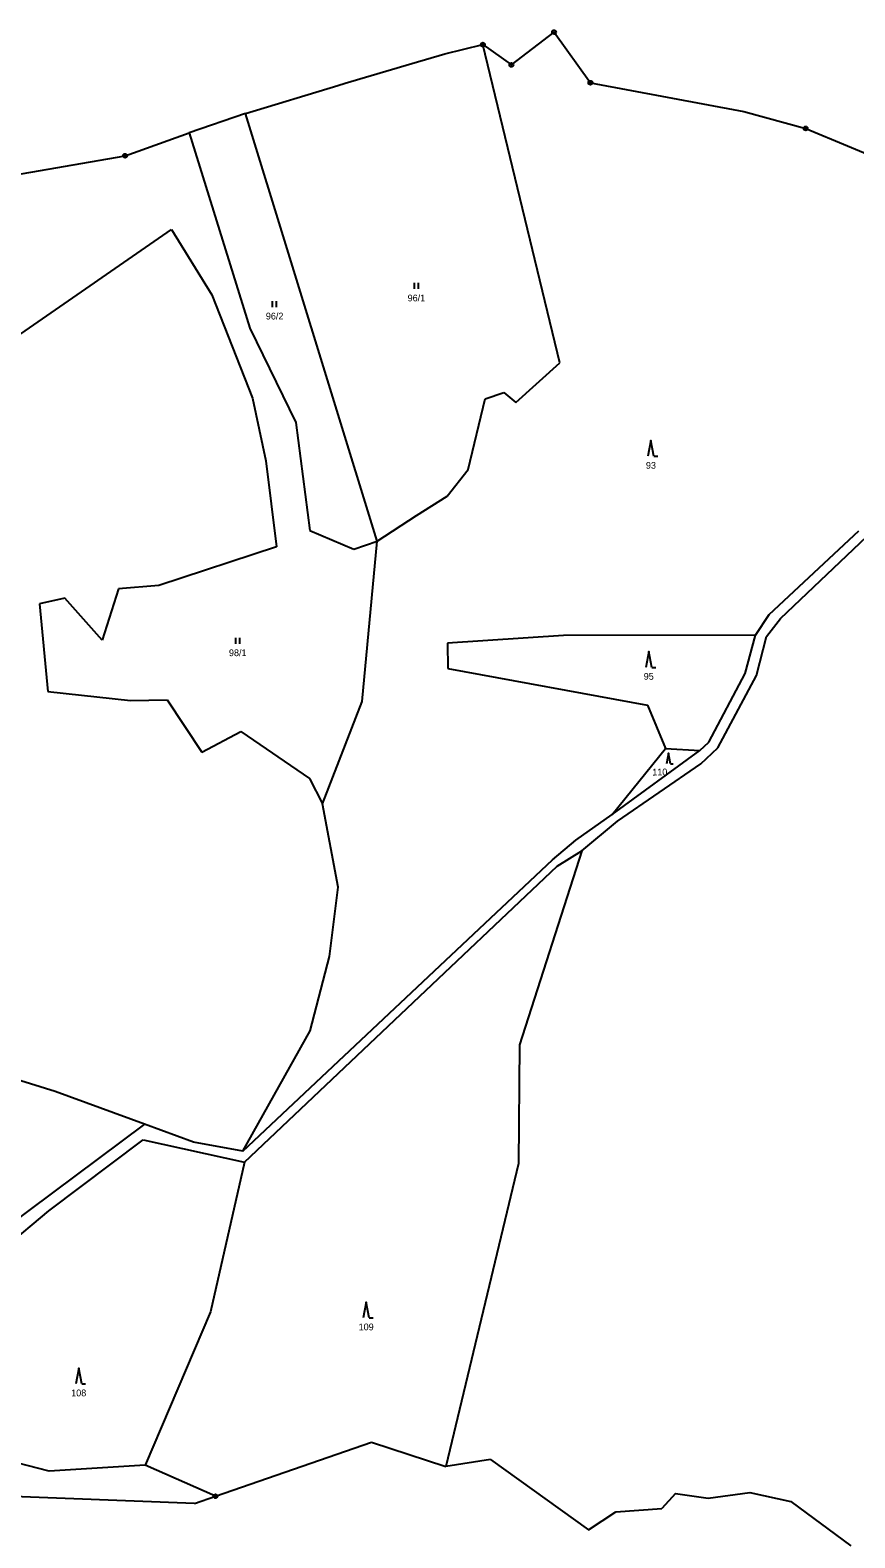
# Model space of a CAD drawing. Extents: x -601877 to -599786, y -1122905 to -1121218.
# Drawn here: x -601684.6 to -601476.9, y -1122139.9 to -1121760.1 of the extents above; entities that cross this region are included whole.
import ezdxf
from ezdxf.enums import TextEntityAlignment as Align

# ---------------------------------------------------------------- set-up
doc = ezdxf.new("R2010")
doc.units = 0
doc.header["$LTSCALE"] = 0.68
for name, color, linetype, lineweight in [('1', 7, 'Continuous', 25), ('3', 7, 'Continuous', 25), ('8', 7, 'Continuous', 25)]:
    doc.layers.add(name, color=color, linetype=linetype, lineweight=lineweight)
doc.layers.add('2', color=7, linetype='Continuous')

msp = doc.modelspace()

# ---------------------------------------------------------------- linework, layer by layer
at = {"layer": '1'}
for p, q in [((-601563.4, -1121768.8), (-601552.65, -1121760.56)), ((-601552.65, -1121760.56), (-601543.5, -1121773.3)), ((-601588.47, -1121768.49), (-601580.13, -1121766.04)), ((-601580.13, -1121766.04), (-601570.58, -1121763.7)), ((-601570.58, -1121763.7), (-601563.4, -1121768.8)), ((-601551.18, -1121843.87), (-601570.58, -1121763.7)), ((-601605.25, -1121773.43), (-601588.47, -1121768.49)), ((-601630.36, -1121781.07), (-601607.07, -1121773.97)), ((-601607.07, -1121773.97), (-601605.25, -1121773.43)), ((-601543.5, -1121773.3), (-601504.87, -1121780.53)), ((-601630.36, -1121781.07), (-601644.55, -1121785.9)), ((-601597.19, -1121888.8), (-601630.36, -1121781.07)), ((-601504.87, -1121780.53), (-601489.29, -1121784.81)), ((-601489.29, -1121784.81), (-601462.41, -1121796.01)), ((-601660.68, -1121791.7), (-601644.55, -1121785.9)), ((-601644.55, -1121785.9), (-601629.23, -1121835.11)), ((-601707.88, -1121799.89), (-601660.68, -1121791.7)), ((-601686.97, -1121836.54), (-601649.03, -1121810.29)), ((-601649.03, -1121810.29), (-601638.8, -1121826.74)), ((-601638.8, -1121826.74), (-601628.63, -1121852.77)), ((-601629.23, -1121835.11), (-601617.68, -1121858.88)), ((-601562.25, -1121853.83), (-601551.18, -1121843.87)), ((-601628.63, -1121852.77), (-601625.22, -1121868.57)), ((-601574.32, -1121870.72), (-601569.99, -1121852.93)), ((-601569.99, -1121852.93), (-601565.33, -1121851.33)), ((-601565.33, -1121851.33), (-601562.25, -1121853.83)), ((-601617.68, -1121858.88), (-601614.16, -1121886.07)), ((-601625.22, -1121868.57), (-601622.52, -1121890.19)), ((-601579.53, -1121877.42), (-601574.32, -1121870.72)), ((-601587.31, -1121882.3), (-601579.53, -1121877.42)), ((-601597.19, -1121888.8), (-601587.31, -1121882.3)), ((-601614.16, -1121886.07), (-601603.05, -1121890.8)), ((-601498.48, -1121907.26), (-601475.94, -1121886.16)), ((-601495.65, -1121908.27), (-601472.22, -1121886.04)), ((-601622.52, -1121890.19), (-601652.22, -1121899.94)), ((-601603.05, -1121890.8), (-601597.19, -1121888.8)), ((-601600.94, -1121929.2), (-601597.19, -1121888.8)), ((-601675.87, -1121903.13), (-601682.19, -1121904.61)), ((-601666.46, -1121913.75), (-601675.87, -1121903.13)), ((-601662.34, -1121900.82), (-601666.46, -1121913.75)), ((-601652.22, -1121899.94), (-601662.34, -1121900.82)), ((-601682.19, -1121904.61), (-601680.1, -1121926.63)), ((-601501.96, -1121912.48), (-601498.48, -1121907.26)), ((-601499.17, -1121912.79), (-601495.65, -1121908.27)), ((-601550.26, -1121912.59), (-601579.52, -1121914.46)), ((-601579.52, -1121914.46), (-601579.41, -1121920.85)), ((-601501.96, -1121912.48), (-601550.26, -1121912.59)), ((-601504.52, -1121922.08), (-601501.96, -1121912.48)), ((-601501.64, -1121922.66), (-601499.17, -1121912.79)), ((-601579.41, -1121920.85), (-601529.14, -1121930.09)), ((-601513.64, -1121939.41), (-601504.52, -1121922.08)), ((-601511.43, -1121940.82), (-601501.64, -1121922.66)), ((-601680.1, -1121926.63), (-601659.31, -1121928.94)), ((-601659.31, -1121928.94), (-601650.07, -1121928.77)), ((-601650.07, -1121928.77), (-601641.38, -1121941.98)), ((-601610.95, -1121954.95), (-601600.94, -1121929.2)), ((-601529.14, -1121930.09), (-601524.6, -1121941.04)), ((-601641.38, -1121941.98), (-601631.49, -1121936.7)), ((-601631.49, -1121936.7), (-601614.22, -1121948.53)), ((-601538.03, -1121957.63), (-601524.6, -1121941.04)), ((-601524.6, -1121941.04), (-601515.92, -1121941.54)), ((-601515.92, -1121941.54), (-601513.64, -1121939.41)), ((-601515.67, -1121944.9), (-601511.43, -1121940.82)), ((-601538.03, -1121957.63), (-601515.92, -1121941.54)), ((-601536.67, -1121959.31), (-601515.67, -1121944.9)), ((-601614.22, -1121948.53), (-601610.95, -1121954.95)), ((-601606.99, -1121975.98), (-601610.95, -1121954.95)), ((-601547.16, -1121964.1), (-601538.03, -1121957.63)), ((-601545.69, -1121966.81), (-601536.67, -1121959.31)), ((-601545.69, -1121966.81), (-601561.35, -1122015.65)), ((-601553.08, -1121969.1), (-601547.16, -1121964.1)), ((-601551.87, -1121970.64), (-601545.69, -1121966.81)), ((-601631.03, -1122042.46), (-601553.08, -1121969.1)), ((-601630.64, -1122045.2), (-601551.87, -1121970.64)), ((-601609.2, -1121993.4), (-601606.99, -1121975.98)), ((-601614.09, -1122012.13), (-601609.2, -1121993.4)), ((-601631.03, -1122042.46), (-601614.09, -1122012.13)), ((-601678.29, -1122027.39), (-601711.28, -1122017.26)), ((-601561.35, -1122015.65), (-601561.61, -1122045.55)), ((-601655.82, -1122035.62), (-601678.29, -1122027.39)), ((-601655.82, -1122035.62), (-601690.54, -1122061.59)), ((-601643.42, -1122040.16), (-601655.82, -1122035.62)), ((-601679.9, -1122057.48), (-601656.12, -1122039.63)), ((-601656.12, -1122039.63), (-601630.64, -1122045.2)), ((-601631.03, -1122042.46), (-601643.42, -1122040.16)), ((-601630.64, -1122045.2), (-601639.18, -1122082.95)), ((-601561.61, -1122045.55), (-601579.93, -1122121.85)), ((-601690.9, -1122066.7), (-601679.9, -1122057.48)), ((-601639.18, -1122082.95), (-601655.62, -1122121.57)), ((-601679.83, -1122123.03), (-601711.13, -1122115.08)), ((-601637.92, -1122129.37), (-601598.61, -1122115.78)), ((-601598.61, -1122115.78), (-601579.93, -1122121.85)), ((-601655.62, -1122121.57), (-601679.83, -1122123.03)), ((-601637.92, -1122129.37), (-601655.62, -1122121.57)), ((-601568.68, -1122120.13), (-601579.93, -1122121.85)), ((-601568.68, -1122120.13), (-601543.94, -1122137.81)), ((-601643.19, -1122131.19), (-601717.39, -1122128.37)), ((-601643.19, -1122131.19), (-601637.92, -1122129.37)), ((-601522.04, -1122128.68), (-601525.53, -1122132.5)), ((-601522.04, -1122128.68), (-601513.86, -1122129.86)), ((-601513.86, -1122129.86), (-601503.35, -1122128.43)), ((-601503.35, -1122128.43), (-601493.03, -1122130.72)), ((-601493.03, -1122130.72), (-601477.88, -1122141.9)), ((-601543.94, -1122137.81), (-601537.1, -1122133.29)), ((-601537.1, -1122133.29), (-601525.53, -1122132.5))]:
    msp.add_line(p, q, dxfattribs=at)
at = {"layer": '3'}
for p, q in [((-601587.831, -1121825.25), (-601587.831, -1121823.75)), ((-601586.83, -1121825.25), (-601586.83, -1121823.75)), ((-601623.531, -1121829.82), (-601623.531, -1121828.32)), ((-601622.53, -1121829.82), (-601622.53, -1121828.32)), ((-601527.51, -1121867.41), (-601526.514, -1121867.41)), ((-601632.821, -1121914.63), (-601632.821, -1121913.13)), ((-601631.82, -1121914.63), (-601631.82, -1121913.13)), ((-601528.06, -1121920.57), (-601527.064, -1121920.57)), ((-601523.318, -1121944.84), (-601522.65, -1121944.84)), ((-601599.22, -1122084.45), (-601598.224, -1122084.45)), ((-601671.6, -1122101.07), (-601670.604, -1122101.07))]:
    msp.add_line(p, q, dxfattribs=at)
for points in [[(-601527.51, -1121867.41), (-601528.26, -1121863.41), (-601529.01, -1121867.41)], [(-601528.06, -1121920.57), (-601528.81, -1121916.57), (-601529.56, -1121920.57)], [(-601523.318, -1121944.84), (-601523.82, -1121942.16), (-601524.322, -1121944.84)], [(-601599.22, -1122084.45), (-601599.97, -1122080.45), (-601600.72, -1122084.45)], [(-601671.6, -1122101.07), (-601672.35, -1122097.07), (-601673.1, -1122101.07)]]:
    msp.add_lwpolyline(points, dxfattribs=at)
at = {"layer": '8'}
for centre, radius in [((-601552.65, -1121760.5599), 0.5), ((-601552.65, -1121760.5599), 0.0303), ((-601570.58, -1121763.6999), 0.5), ((-601570.58, -1121763.6999), 0.0303), ((-601563.4, -1121768.7999), 0.5), ((-601563.4, -1121768.7999), 0.0303), ((-601543.5, -1121773.2999), 0.5), ((-601543.5, -1121773.2999), 0.0303), ((-601489.29, -1121784.8099), 0.5), ((-601489.29, -1121784.8099), 0.0303), ((-601660.68, -1121791.6999), 0.5), ((-601660.68, -1121791.6999), 0.0303), ((-601637.92, -1122129.3699), 0.5), ((-601637.92, -1122129.3699), 0.0303)]:
    msp.add_circle(centre, radius, dxfattribs=at)

# ---------------------------------------------------------------- texts
at = {"layer": '2'}
for s, p in [('96/1', (-601587.319, -1121828.375)), ('96/2', (-601623.019, -1121832.945)), ('93', (-601528.259, -1121870.535)), ('98/1', (-601632.309, -1121917.755)), ('95', (-601528.809, -1121923.695)), ('109', (-601599.969, -1122087.575)), ('108', (-601672.349, -1122104.195))]:
    msp.add_text(s, height=1.7, dxfattribs=at).set_placement(p, align=Align.CENTER)
msp.add_text('110', height=1.7, rotation=1, dxfattribs=at).set_placement((-601526.0148, -1121947.7939), align=Align.CENTER)

doc.saveas('drawing.dxf')
